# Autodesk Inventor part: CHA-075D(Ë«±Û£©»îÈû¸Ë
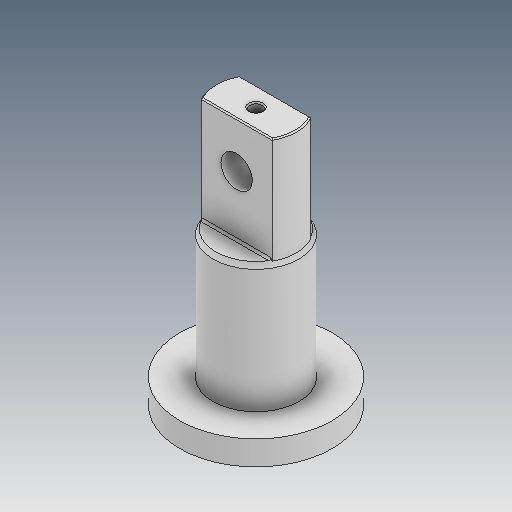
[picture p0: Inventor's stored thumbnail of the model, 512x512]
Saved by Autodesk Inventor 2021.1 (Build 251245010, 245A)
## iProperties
Created: 2021-05
Part Number: CHA-075D(Ë«±Û£©»îÈû¸Ë
Material: Ogólny
Document SubType Name: Modeling
Designer: user
Density: 1 g/cm^3
Appearance: Domyślna
Author: user
Revision Number: ÈÎºÎ
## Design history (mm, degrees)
feature "ÊäÈë1"
node "Bryła1"
